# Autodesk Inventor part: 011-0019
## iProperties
Created: 2007-02
Part Number: 011-0019
Document SubType Name: Modeling
Designer: GG5883
Description: Levier de serrage
Stock Number: 11-0019
Material: 34 Cr Mo 4
Checked By: GG5883
Author: GG5883
Revision Number: 00
Title: LEVIER DE SERRAGE
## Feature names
1. Révolution1 [Revolution]
2. Révolution2 [Revolution]
3. Révolution3 [Revolution]
4. Scission1
5. Dépouille de face1
6. Dépouille de face2
7. Chanfrein1 [Chamfer]
